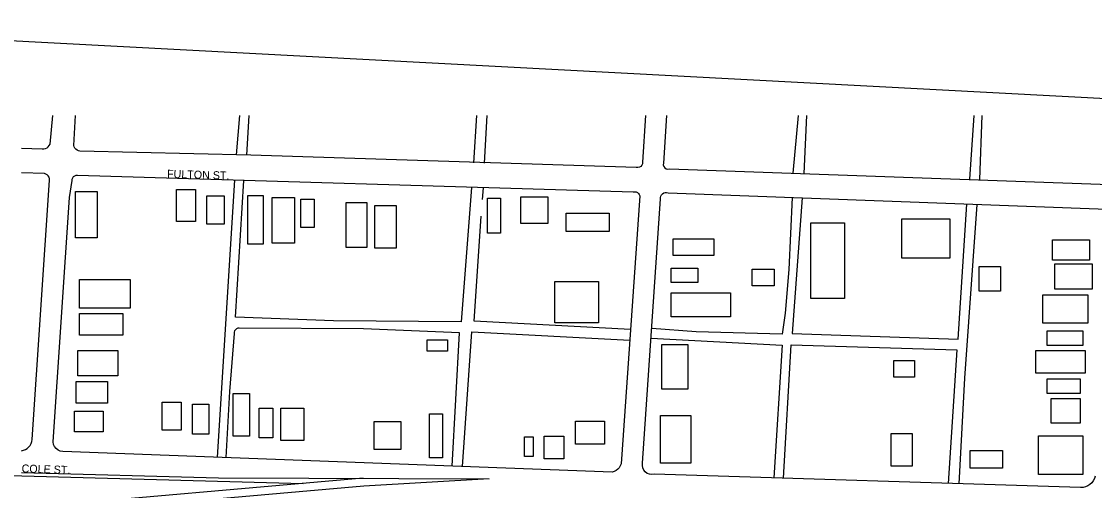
# Model space of a CAD drawing. Extents: x -9648 to 41057, y -12373 to 40276.
# Drawn here: x 14546 to 15887, y -4925 to -4339 of the extents above; entities that cross this region are included whole.
import ezdxf

# ---------------------------------------------------------------- set-up
doc = ezdxf.new("R2010")
doc.units = 0
doc.layers.add('SC_Scratch1', color=7, linetype='Continuous')
doc.layers.add('SH_Data', color=7, linetype='Continuous')

msp = doc.modelspace()

# ---------------------------------------------------------------- linework, layer by layer
at = {"layer": 'SC_Scratch1'}
msp.add_line((15927.4, -4436.9), (14069.8, -4338.8), dxfattribs=at)
at = {"layer": 'SH_Data'}
for p, q in [((14581.9, -4491.9), (14585.3, -4456.3)), ((14611.5, -4493.7), (14613.7, -4456.3)), ((14818.5, -4456.3), (14814.5, -4505.3)), ((14827.9, -4505.6), (14830.7, -4456.3)), ((15111.3, -4515.2), (15115.1, -4456.3)), ((15124.9, -4515.7), (15127.9, -4456.3)), ((15325.9, -4456.3), (15322.3, -4514.5)), ((15352.1, -4456.3), (15348.3, -4515.9)), ((15516.9, -4456.3), (15510.1, -4528.3)), ((15524.1, -4528.8), (15527.7, -4456.3)), ((15736.1, -4456.3), (15730.8, -4535.8)), ((15743.7, -4536.2), (15746.7, -4456.3)), ((14580.9, -4493.7), (14581.9, -4491.9)), ((14546.1, -4497.1), (14572.1, -4497.9)), ((14572.1, -4497.9), (14574.1, -4497.8)), ((14574.1, -4497.8), (14576.1, -4497.3)), ((14576.1, -4497.3), (14578, -4496.5)), ((14578, -4496.5), (14579.6, -4495.2)), ((14579.6, -4495.2), (14580.9, -4493.7)), ((14612, -4495.5), (14611.5, -4493.7)), ((14612.9, -4497.1), (14612, -4495.5)), ((14614.1, -4498.5), (14612.9, -4497.1)), ((14615.6, -4499.6), (14614.1, -4498.5)), ((14617.3, -4500.3), (14615.6, -4499.6)), ((14619.1, -4500.7), (14617.3, -4500.3)), ((14832.7, -4505.7), (14619.1, -4500.7)), ((15314.3, -4521.1), (14832.7, -4505.7)), ((15321.4, -4518.4), (15320.1, -4519.9)), ((15322.2, -4516.5), (15321.4, -4518.4)), ((15322.3, -4514.5), (15322.2, -4516.5)), ((15348.3, -4515.9), (15348.2, -4518)), ((15348.2, -4518), (15348.9, -4520)), ((14574.7, -4528.9), (14546.1, -4527.9)), ((14576.6, -4529.4), (14574.7, -4528.9)), ((14578.3, -4530.3), (14576.6, -4529.4)), ((14579.6, -4531.6), (14578.3, -4530.3)), ((14580.6, -4533.3), (14579.6, -4531.6)), ((14610.1, -4534), (14611.1, -4532.5)), ((14611.1, -4532.5), (14612.6, -4531.4)), ((14612.6, -4531.4), (14614.3, -4530.8)), ((14614.3, -4530.8), (14616.1, -4530.7)), ((14616.1, -4530.7), (15310.7, -4551.7)), ((15316.3, -4521.4), (15314.3, -4521.1)), ((15318.3, -4520.9), (15316.3, -4521.4)), ((15320.1, -4519.9), (15318.3, -4520.9)), ((15348.9, -4520), (15350.2, -4521.6)), ((15350.2, -4521.6), (15351.9, -4522.7)), ((15351.9, -4522.7), (15354, -4523.2)), ((15354, -4523.2), (15356, -4522.9)), ((15356, -4522.9), (15905.9, -4542.3)), ((14559.5, -4860.9), (14581.1, -4537.1)), ((14581.1, -4535.2), (14580.6, -4533.3)), ((14581.1, -4537.1), (14581.1, -4535.2)), ((14606.1, -4558.5), (14609.5, -4537.5)), ((14609.5, -4535.7), (14610.1, -4534)), ((14609.5, -4537.5), (14609.5, -4535.7)), ((14812.3, -4537), (14790.7, -4883.1)), ((14813.5, -4708.1), (14824.1, -4537.3)), ((15108.3, -4546.1), (15095.5, -4714.1)), ((14585.7, -4863.9), (14606.1, -4558.5)), ((15122.4, -4561.3), (15123.7, -4546.5)), ((15318.7, -4556.7), (15295.5, -4891.5)), ((15310.7, -4551.7), (15312.5, -4551.4)), ((15312.5, -4551.4), (15314.2, -4551.6)), ((15314.2, -4551.6), (15315.9, -4552.3)), ((15315.9, -4552.3), (15317.3, -4553.5)), ((15317.3, -4553.5), (15318.2, -4555)), ((15318.2, -4555), (15318.7, -4556.7)), ((15344.7, -4558.7), (15345.1, -4556.9)), ((15344.7, -4560.5), (15344.7, -4558.7)), ((15345.1, -4556.9), (15345.9, -4555.3)), ((15345.9, -4555.3), (15347.2, -4554)), ((15347.2, -4554), (15348.8, -4553)), ((15348.8, -4553), (15350.5, -4552.5)), ((15350.5, -4552.5), (15352.3, -4552.5)), ((15352.3, -4552.5), (15354.1, -4552.9)), ((15354.1, -4552.9), (15902.9, -4573.3)), ((15509.3, -4558.7), (15504.9, -4648.5)), ((15521.7, -4559.1), (15509.1, -4728.7)), ((15322.3, -4890.5), (15344.7, -4560.5)), ((15716.7, -4735.7), (15727.5, -4566.8)), ((15724.9, -4784.3), (15740.5, -4567.3)), ((15111.9, -4713.1), (15120.5, -4582)), ((15504.9, -4648.5), (15500.5, -4703.3)), ((15500.5, -4703.3), (15496.7, -4729.5)), ((14935.9, -4712.7), (14813.5, -4708.1)), ((15095.5, -4714.1), (14935.9, -4712.7)), ((15307.1, -4723.5), (15111.9, -4713.1)), ((14811.7, -4728.5), (14805.9, -4800.9)), ((14811.9, -4726.8), (14811.7, -4728.5)), ((14812.5, -4725.2), (14811.9, -4726.8)), ((14813.5, -4723.8), (14812.5, -4725.2)), ((14814.9, -4722.7), (14813.5, -4723.8)), ((14816.4, -4722), (14814.9, -4722.7)), ((14818.1, -4721.7), (14816.4, -4722)), ((14973.5, -4722.9), (14818.1, -4721.7)), ((15093.5, -4727.7), (14973.5, -4722.9)), ((15084.3, -4894.2), (15093.5, -4727.7)), ((15097.3, -4894.7), (15108.9, -4726.3)), ((15108.9, -4726.3), (15306.2, -4736.9)), ((15389.1, -4726.3), (15333.7, -4722.5)), ((15496.7, -4729.5), (15389.1, -4726.3)), ((15509.1, -4728.7), (15716.7, -4735.7)), ((15332.9, -4734.3), (15496.7, -4743.3)), ((15496.7, -4743.3), (15486.3, -4909)), ((15498.5, -4909.3), (15508.1, -4742.5)), ((15508.1, -4742.5), (15715.1, -4748.9)), ((15715.1, -4748.9), (15704.3, -4915.7)), ((15718.1, -4916.2), (15724.9, -4784.3)), ((14805.9, -4800.9), (14801.5, -4883.5)), ((14556.9, -4868.3), (14558.2, -4866)), ((14558.2, -4866), (14559.1, -4863.5)), ((14559.1, -4863.5), (14559.5, -4860.9)), ((14586.2, -4867), (14585.7, -4863.9)), ((14587.4, -4869.8), (14586.2, -4867)), ((14546.1, -4874.9), (14548.7, -4874.4)), ((14548.7, -4874.4), (14551.1, -4873.4)), ((14551.1, -4873.4), (14553.3, -4872)), ((14553.3, -4872), (14555.3, -4870.3)), ((14555.3, -4870.3), (14556.9, -4868.3)), ((14589.3, -4872.3), (14587.4, -4869.8)), ((14591.8, -4874.2), (14589.3, -4872.3)), ((14594.6, -4875.4), (14591.8, -4874.2)), ((14597.7, -4875.9), (14594.6, -4875.4)), ((15284.3, -4901.7), (14597.7, -4875.9)), ((14060.3, -4893), (14898.1, -4915.8)), ((15294.5, -4893.9), (15293.1, -4896.2)), ((15295.5, -4891.5), (15294.5, -4893.9)), ((15322, -4893.5), (15322.3, -4890.5)), ((15322.5, -4896.4), (15322, -4893.5)), ((14546.1, -4902.1), (14792.3, -4908.9)), ((15286.8, -4900.9), (15284.3, -4901.7)), ((15289.2, -4899.7), (15286.8, -4900.9)), ((15291.3, -4898.1), (15289.2, -4899.7)), ((15293.1, -4896.2), (15291.3, -4898.1)), ((15323.8, -4899.1), (15322.5, -4896.4)), ((15325.6, -4901.4), (15323.8, -4899.1)), ((15328, -4903.2), (15325.6, -4901.4)), ((15330.8, -4904.3), (15328, -4903.2)), ((15333.7, -4904.7), (15330.8, -4904.3)), ((15336.7, -4904.3), (15333.7, -4904.7)), ((15869.7, -4920.9), (15336.7, -4904.3)), ((15888.1, -4906.9), (15887.1, -4909.8)), ((14973.2, -4909.3), (14545.2, -4946.5)), ((14974.1, -4919.3), (14546.1, -4956.5)), ((14792.3, -4908.9), (15130.7, -4910.1)), ((15130.7, -4910.1), (14974.1, -4919.3)), ((15872.8, -4920.7), (15869.7, -4920.9)), ((15875.8, -4920), (15872.8, -4920.7)), ((15878.7, -4918.8), (15875.8, -4920)), ((15881.3, -4917.1), (15878.7, -4918.8)), ((15883.6, -4915), (15881.3, -4917.1)), ((15885.6, -4912.6), (15883.6, -4915)), ((15887.1, -4909.8), (15885.6, -4912.6))]:
    msp.add_line(p, q, dxfattribs=at)
for points in [[(14613.7, -4551.3), (14640.8, -4551.3), (14640.8, -4608.9), (14613.7, -4608.9)], [(14739.7, -4548.6), (14763.4, -4548.6), (14763.4, -4588.5), (14739.7, -4588.5)], [(14777.6, -4556.7), (14799.3, -4556.7), (14799.3, -4591.9), (14777.6, -4591.9)], [(14829.1, -4556), (14848, -4556), (14848, -4617), (14829.1, -4617)], [(14859.5, -4558.7), (14887.3, -4558.7), (14887.3, -4615.6), (14859.5, -4615.6)], [(15128.6, -4559.3), (15144.6, -4559.3), (15144.6, -4603.4), (15128.6, -4603.4)], [(15170.3, -4558), (15204.1, -4558), (15204.1, -4591.2), (15170.3, -4591.2)], [(14895.4, -4560.8), (14911.7, -4560.8), (14911.7, -4596), (14895.4, -4596)], [(14951.9, -4564.8), (14977.7, -4564.8), (14977.7, -4621.2), (14951.9, -4621.2)], [(14987.5, -4568.5), (15014.5, -4568.5), (15014.5, -4621.9), (14987.5, -4621.9)], [(15226.8, -4578.3), (15280.7, -4578.3), (15280.7, -4601), (15226.8, -4601)], [(15646.4, -4585.5), (15706.4, -4585.5), (15706.4, -4634.5), (15646.4, -4634.5)], [(15532.7, -4590.2), (15574.6, -4590.2), (15574.6, -4685), (15532.7, -4685)], [(15360.5, -4610.2), (15411.4, -4610.2), (15411.4, -4631.1), (15360.5, -4631.1)], [(15834.4, -4611.6), (15880.9, -4611.6), (15880.9, -4636.8), (15834.4, -4636.8)], [(15358, -4647), (15391.2, -4647), (15391.2, -4664.8), (15358, -4664.8)], [(15459.3, -4648.2), (15486.9, -4648.2), (15486.9, -4669.1), (15459.3, -4669.1)], [(15742.8, -4644.7), (15769.6, -4644.7), (15769.6, -4675.6), (15742.8, -4675.6)], [(15837.5, -4641.6), (15884.1, -4641.6), (15884.1, -4673.2), (15837.5, -4673.2)], [(14618.4, -4661), (14682.1, -4661), (14682.1, -4696.9), (14618.4, -4696.9)], [(15212.6, -4663.6), (15267.2, -4663.6), (15267.2, -4715.1), (15212.6, -4715.1)], [(15358, -4677.7), (15432.3, -4677.7), (15432.3, -4707.8), (15358, -4707.8)], [(15822.5, -4680.3), (15878.6, -4680.3), (15878.6, -4715.8), (15822.5, -4715.8)], [(14618.4, -4703.7), (14672.6, -4703.7), (14672.6, -4730.8), (14618.4, -4730.8)], [(15828, -4725.3), (15872.3, -4725.3), (15872.3, -4743.5), (15828, -4743.5)], [(15053.1, -4736.6), (15078.3, -4736.6), (15078.3, -4750.7), (15053.1, -4750.7)], [(15346.4, -4742.1), (15378.9, -4742.1), (15378.9, -4798), (15346.4, -4798)], [(14616.4, -4749.8), (14666.5, -4749.8), (14666.5, -4781.6), (14616.4, -4781.6)], [(15813.8, -4749.8), (15875.4, -4749.8), (15875.4, -4778.2), (15813.8, -4778.2)], [(15636.2, -4762.4), (15662.2, -4762.4), (15662.2, -4783), (15636.2, -4783)], [(15828, -4785.3), (15869.1, -4785.3), (15869.1, -4803.5), (15828, -4803.5)], [(14614.4, -4788.4), (14653.6, -4788.4), (14653.6, -4815.5), (14614.4, -4815.5)], [(14722.1, -4814.2), (14745.8, -4814.2), (14745.8, -4849.4), (14722.1, -4849.4)], [(14810.8, -4803.3), (14831.1, -4803.3), (14831.1, -4856.8), (14810.8, -4856.8)], [(15832.8, -4809.8), (15869.1, -4809.8), (15869.1, -4840.6), (15832.8, -4840.6)], [(14612.3, -4825.7), (14648.2, -4825.7), (14648.2, -4851.4), (14612.3, -4851.4)], [(14760, -4816.9), (14780.3, -4816.9), (14780.3, -4854.1), (14760, -4854.1)], [(14843.3, -4821.6), (14860.2, -4821.6), (14860.2, -4858.9), (14843.3, -4858.9)], [(14870.4, -4821.6), (14898.8, -4821.6), (14898.8, -4862.3), (14870.4, -4862.3)], [(14986.9, -4838.5), (15020, -4838.5), (15020, -4873.5), (14986.9, -4873.5)], [(15056.2, -4828.7), (15072.2, -4828.7), (15072.2, -4883.9), (15056.2, -4883.9)], [(15238.4, -4837.9), (15274.6, -4837.9), (15274.6, -4866.7), (15238.4, -4866.7)], [(15344.5, -4831.1), (15382.6, -4831.1), (15382.6, -4890.6), (15344.5, -4890.6)], [(15633, -4853.3), (15659.1, -4853.3), (15659.1, -4894.3), (15633, -4894.3)], [(15174.6, -4857.5), (15185.7, -4857.5), (15185.7, -4882), (15174.6, -4882)], [(15199.2, -4856.9), (15223.7, -4856.9), (15223.7, -4885.1), (15199.2, -4885.1)], [(15817, -4856.4), (15872.3, -4856.4), (15872.3, -4904.6), (15817, -4904.6)], [(15731.7, -4874.6), (15772, -4874.6), (15772, -4896.7), (15731.7, -4896.7)]]:
    msp.add_lwpolyline(points, close=True, dxfattribs=at)

# ---------------------------------------------------------------- texts
at = {"layer": 'SC_Scratch1'}
for s, rotation, p in [('FULTON ST.', 358.2683, (14727.9, -4534)), ('COLE ST.', 358.0242, (14546.1, -4902))]:
    msp.add_text(s, height=10, rotation=rotation, dxfattribs=at).set_placement(p)

doc.saveas('drawing.dxf')
